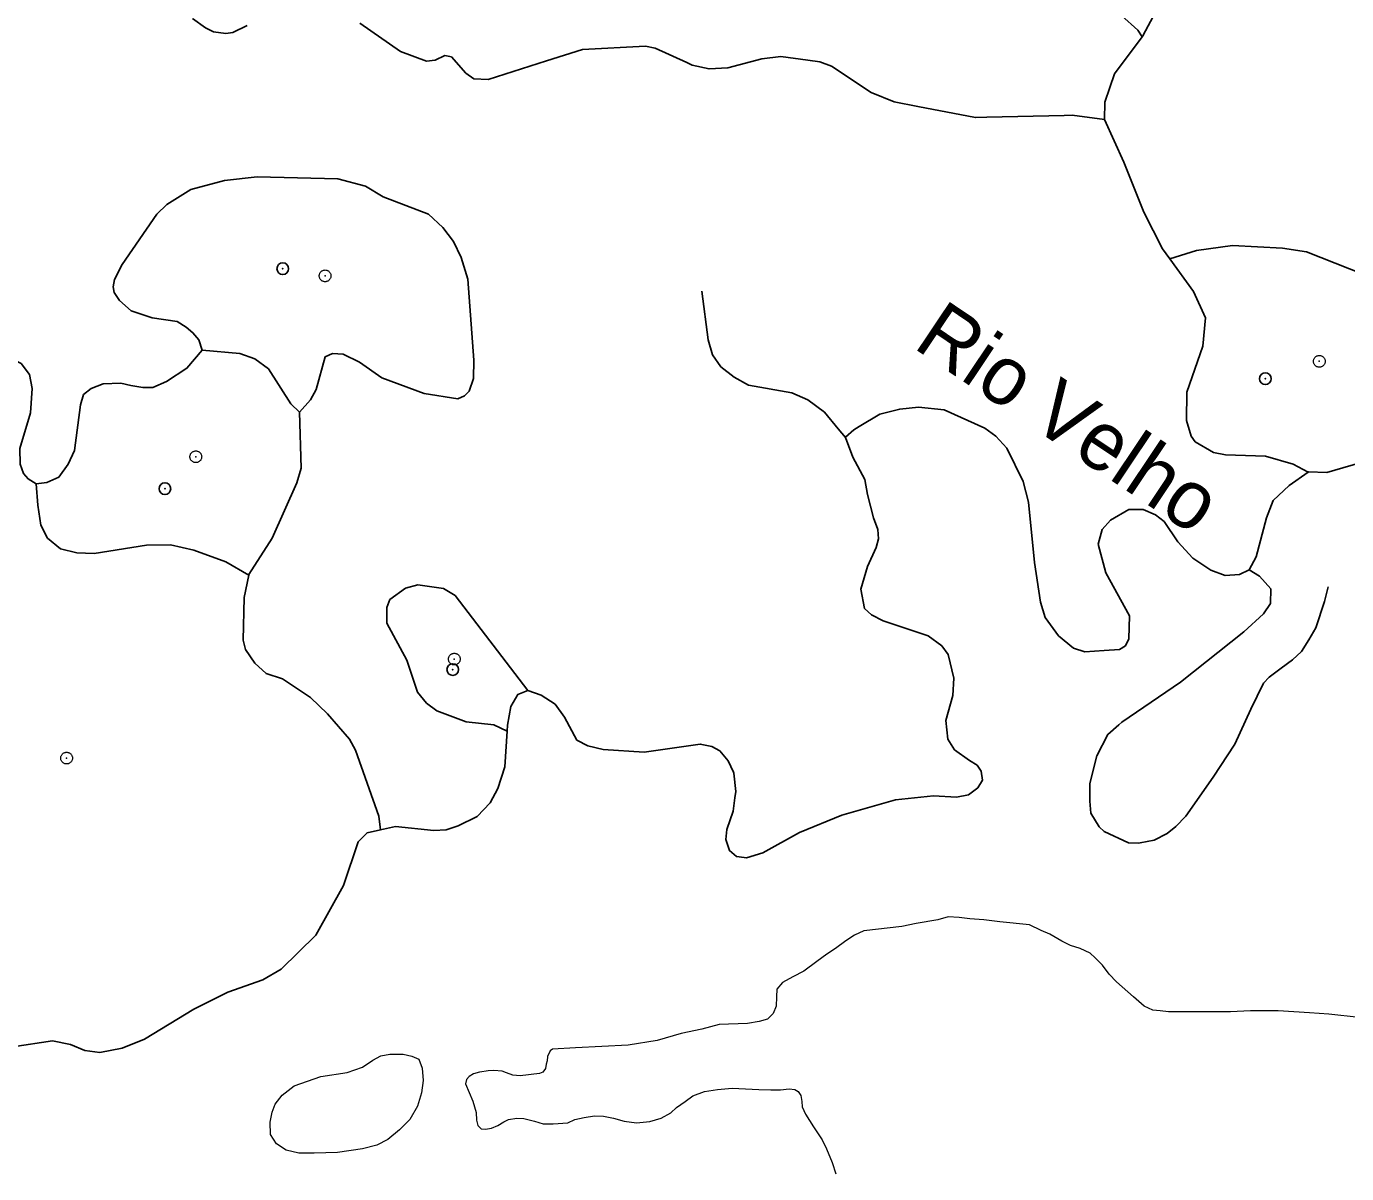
# Model space of a CAD drawing. Extents: x 267.7 to 296, y 7537.7 to 7565.8.
# Drawn here: x 272.267 to 274.519, y 7553.465 to 7555.422 of the extents above; entities that cross this region are included whole.
import ezdxf
from ezdxf.enums import TextEntityAlignment as Align

# ---------------------------------------------------------------- set-up
doc = ezdxf.new("R2010")
doc.units = 0
doc.header["$LTSCALE"] = 0.04
doc.header["$PDMODE"] = 32
doc.header["$PDSIZE"] = 0.02
doc.linetypes.add('SHORT_DASHED', pattern=[2.7, 1.5, -1.2])
doc.layers.add('21', color=7, linetype='SHORT_DASHED', lineweight=13)
doc.layers.add('7', color=7, linetype='Continuous', lineweight=25)
doc.layers.add('54', color=7, linetype='Continuous')
doc.layers.add('61', color=7, linetype='Continuous')

msp = doc.modelspace()

# ---------------------------------------------------------------- linework, layer by layer
at = {"layer": '21'}
for points in [[(274.5405, 7553.7312), (274.4887, 7553.7371), (274.4554, 7553.7394), (274.4022, 7553.7423), (274.3548, 7553.7423), (274.3208, 7553.7408), (274.2535, 7553.7408), (274.2306, 7553.7408), (274.2151, 7553.7408), (274.201, 7553.7423), (274.1884, 7553.7438), (274.1736, 7553.7504), (274.1552, 7553.7667), (274.1263, 7553.7919), (274.1137, 7553.8052), (274.1027, 7553.8207), (274.0901, 7553.8333), (274.0812, 7553.8407), (274.0642, 7553.8488), (274.0479, 7553.854), (274.0331, 7553.8614), (274.0124, 7553.8732), (273.9976, 7553.8799), (273.9777, 7553.8895), (273.9274, 7553.8947), (273.9, 7553.8976), (273.8764, 7553.8998), (273.8579, 7553.9021), (273.8394, 7553.9028), (273.8216, 7553.8976), (273.7847, 7553.8917), (273.7602, 7553.8865), (273.6952, 7553.8791), (273.6796, 7553.8717), (273.6648, 7553.8621), (273.6471, 7553.8488), (273.6323, 7553.8392), (273.6153, 7553.8266), (273.5931, 7553.8104)], [(273.5931, 7553.8104), (273.5746, 7553.8007), (273.5569, 7553.7911), (273.5473, 7553.7793), (273.5465, 7553.7667), (273.5458, 7553.7504)], [(273.5458, 7553.7504), (273.5406, 7553.7379), (273.531, 7553.7283), (273.5169, 7553.7246), (273.497, 7553.7209), (273.4489, 7553.7194), (273.4193, 7553.7113), (273.3838, 7553.7039), (273.3432, 7553.692), (273.2936, 7553.6839), (273.2034, 7553.6795), (273.1642, 7553.6772), (273.1605, 7553.6743), (273.156, 7553.6647), (273.1553, 7553.6573), (273.1538, 7553.6514), (273.1524, 7553.644), (273.1479, 7553.638), (273.142, 7553.6358), (273.1095, 7553.6314), (273.0969, 7553.6329), (273.0858, 7553.6366), (273.0784, 7553.6395), (273.0643, 7553.641), (273.0547, 7553.6403), (273.0407, 7553.638), (273.0399, 7553.638), (273.0296, 7553.6351), (273.0222, 7553.6306), (273.0178, 7553.6255), (273.0163, 7553.6181), (273.0222, 7553.6033), (273.0288, 7553.5885), (273.034, 7553.5693), (273.0348, 7553.556), (273.0372, 7553.5467), (273.0429, 7553.5412), (273.0503, 7553.5404), (273.0606, 7553.5426), (273.071, 7553.5471), (273.0814, 7553.553), (273.0895, 7553.5574), (273.1035, 7553.5596), (273.1154, 7553.5589), (273.1339, 7553.5545), (273.1487, 7553.55), (273.1657, 7553.55), (273.1908, 7553.5515), (273.2026, 7553.5574), (273.2182, 7553.5604), (273.2359, 7553.5633), (273.2514, 7553.5626), (273.2685, 7553.5596), (273.2869, 7553.5545), (273.3077, 7553.5515), (273.3306, 7553.5537), (273.3498, 7553.5596), (273.3661, 7553.5685), (273.3757, 7553.5774), (273.3905, 7553.5878), (273.4038, 7553.5974), (273.4238, 7553.6048), (273.4459, 7553.6085), (273.4711, 7553.6107), (273.5162, 7553.6085), (273.5369, 7553.6077), (273.5532, 7553.6077), (273.568, 7553.6092), (273.5776, 7553.6085), (273.5835, 7553.6048), (273.5879, 7553.5981), (273.5894, 7553.5878), (273.5902, 7553.5789), (273.5961, 7553.5663), (273.6094, 7553.5449), (273.6242, 7553.5227), (273.6316, 7553.5071), (273.6412, 7553.4835), (273.6478, 7553.4642)]]:
    msp.add_lwpolyline(points, dxfattribs=at)
msp.add_lwpolyline([(272.732, 7553.4997), (272.71, 7553.5048), (272.6938, 7553.5158), (272.6835, 7553.5313), (272.6827, 7553.5526), (272.6864, 7553.5695), (272.6916, 7553.5835), (272.7033, 7553.5989), (272.7239, 7553.6144), (272.7695, 7553.6306), (272.8144, 7553.6372), (272.8401, 7553.6467), (272.8578, 7553.6585), (272.8717, 7553.6659), (272.8872, 7553.6688), (272.91, 7553.6688), (272.9247, 7553.6651), (272.9364, 7553.66), (272.9423, 7553.6445), (272.9438, 7553.6239), (272.9408, 7553.6026), (272.9342, 7553.5798), (272.921, 7553.557), (272.9033, 7553.5394), (272.8835, 7553.5232), (272.8651, 7553.5136), (272.8401, 7553.507), (272.7975, 7553.5011), (272.7577, 7553.4997)], close=True, dxfattribs=at)
for p in [(272.7766, 7554.9968), (274.4722, 7554.851), (272.5561, 7554.6881), (272.997, 7554.3428), (272.3357, 7554.1738)]:
    msp.add_point(p, dxfattribs=at)
at = {"layer": '54'}
for p in [(272.7044, 7555.009), (274.3802, 7554.8213), (272.5033, 7554.6336), (272.9943, 7554.325)]:
    msp.add_point(p, dxfattribs=at)
at = {"layer": '7'}
for points in [[(274.1702, 7555.4048), (274.1713, 7555.4063), (274.1936, 7555.448), (274.1997, 7555.4594), (274.2058, 7555.4909), (274.2053, 7555.5587), (274.1908, 7555.6607), (274.1948, 7555.6876), (274.2191, 7555.7468), (274.2384, 7555.782)], [(273.9763, 7555.6484), (273.9954, 7555.6071), (274.0194, 7555.5646), (274.0368, 7555.5161), (274.0447, 7555.5036), (274.0653, 7555.4858), (274.0662, 7555.4849), (274.0939, 7555.4664), (274.1351, 7555.441), (274.163, 7555.4162), (274.1702, 7555.4048)], [(272.5502, 7555.4357), (272.5728, 7555.4203), (272.5861, 7555.4131), (272.6074, 7555.4103), (272.6195, 7555.4122), (272.6436, 7555.4239)], [(272.836, 7555.4282), (272.9053, 7555.3794), (272.9495, 7555.3633), (272.9642, 7555.365), (272.9809, 7555.3727), (272.9923, 7555.3705)], [(274.1058, 7555.2637), (274.1062, 7555.293), (274.1148, 7555.3182), (274.1227, 7555.3413), (274.1702, 7555.4048)], [(272.9923, 7555.3705), (273.0166, 7555.3427), (273.0301, 7555.3331), (273.0547, 7555.3319), (273.1543, 7555.3635), (273.2154, 7555.3828)], [(273.2154, 7555.3828), (273.323, 7555.3887), (273.3395, 7555.3854), (273.3934, 7555.3608), (273.4029, 7555.3565), (273.4315, 7555.3499), (273.4637, 7555.3517), (273.5217, 7555.3672), (273.5539, 7555.3713), (273.5997, 7555.365), (273.6205, 7555.3622), (273.6403, 7555.3546), (273.7079, 7555.3096), (273.7472, 7555.2937), (273.7878, 7555.2858), (273.8857, 7555.2669), (273.9054, 7555.2674), (274.0371, 7555.2706), (274.051, 7555.2709), (274.1058, 7555.2637)], [(274.2172, 7555.026), (274.2049, 7555.0429), (274.1729, 7555.1052), (274.1391, 7555.191), (274.1058, 7555.2637)], [(272.7329, 7554.7642), (272.7518, 7554.7855), (272.7615, 7554.803), (272.7767, 7554.8584), (272.7891, 7554.8645), (272.8074, 7554.8632), (272.8354, 7554.8493), (272.8736, 7554.8225), (272.9453, 7554.7962), (273.0031, 7554.7869), (273.0145, 7554.7921), (273.0225, 7554.8), (273.0298, 7554.8218), (273.0301, 7554.8527), (273.0203, 7554.991), (273.0088, 7555.0283), (272.9954, 7555.0555), (272.9775, 7555.0794), (272.9528, 7555.1019), (272.8758, 7555.1314), (272.8456, 7555.15), (272.7984, 7555.1626), (272.661, 7555.1656), (272.6051, 7555.1593), (272.5476, 7555.144), (272.5069, 7555.1185), (272.4895, 7555.102), (272.4304, 7555.0163), (272.4176, 7554.9906), (272.4151, 7554.9778), (272.417, 7554.9683), (272.4258, 7554.9549), (272.4456, 7554.937), (272.4817, 7554.925), (272.5244, 7554.9188), (272.5399, 7554.9091), (272.5511, 7554.8996), (272.5615, 7554.8875), (272.5667, 7554.8698)], [(274.6963, 7554.9579), (274.6766, 7554.9575), (274.6187, 7554.9714), (274.4505, 7555.0376), (274.4097, 7555.0441), (274.3243, 7555.0487), (274.2629, 7555.0399), (274.2172, 7555.026)], [(274.4531, 7554.6619), (274.4275, 7554.6755), (274.3805, 7554.6891), (274.3124, 7554.6912), (274.2916, 7554.6952), (274.2603, 7554.7137), (274.2535, 7554.7231), (274.246, 7554.7498), (274.2464, 7554.7985), (274.2738, 7554.8766), (274.2783, 7554.9253), (274.2579, 7554.9701), (274.2172, 7555.026)], [(273.419, 7554.9704), (273.4302, 7554.8875), (273.4375, 7554.8623), (273.4516, 7554.8417), (273.4742, 7554.8238), (273.4985, 7554.8101), (273.5724, 7554.7971), (273.5998, 7554.7855), (273.6281, 7554.7642), (273.6517, 7554.736), (273.6641, 7554.7211)], [(272.2003, 7554.8681), (272.2146, 7554.868), (272.2296, 7554.8621), (272.2581, 7554.8472), (272.2727, 7554.8282), (272.2772, 7554.8043), (272.2739, 7554.7629), (272.2557, 7554.7022), (272.2564, 7554.6755), (272.2621, 7554.6598), (272.27, 7554.6504), (272.284, 7554.6418)], [(272.284, 7554.6418), (272.3018, 7554.6443), (272.3223, 7554.6535), (272.3381, 7554.6755), (272.3494, 7554.6986), (272.3593, 7554.7767), (272.3644, 7554.7941), (272.3778, 7554.8044), (272.3983, 7554.8126), (272.4281, 7554.8136), (272.4455, 7554.8095), (272.466, 7554.8065), (272.4825, 7554.8065), (272.5061, 7554.8167), (272.5409, 7554.8391), (272.5667, 7554.8698)], [(272.5667, 7554.8698), (272.6313, 7554.8641), (272.6567, 7554.8553), (272.6802, 7554.8381), (272.7184, 7554.7784), (272.7329, 7554.7642)], [(272.7329, 7554.7642), (272.733, 7554.7641), (272.7356, 7554.6689), (272.7282, 7554.6434), (272.6863, 7554.5494), (272.6467, 7554.4874), (272.6465, 7554.4862)], [(273.6641, 7554.7211), (273.6639, 7554.7216), (273.6781, 7554.7343), (273.6877, 7554.74), (273.7227, 7554.7608), (273.7566, 7554.7695), (273.7885, 7554.7728), (273.8324, 7554.7679), (273.9017, 7554.7369), (273.9208, 7554.7233), (273.9391, 7554.7029), (273.9669, 7554.6459), (273.9761, 7554.6106), (273.9863, 7554.5076), (273.9969, 7554.4399), (274.0047, 7554.4136), (274.0276, 7554.3823), (274.0533, 7554.3615), (274.0721, 7554.3554), (274.1051, 7554.3576), (274.1314, 7554.3593), (274.1415, 7554.3655), (274.1476, 7554.3775), (274.1488, 7554.4169), (274.108, 7554.4902), (274.0951, 7554.5389), (274.1017, 7554.564), (274.1164, 7554.58), (274.1474, 7554.5979), (274.172, 7554.5979), (274.193, 7554.5892), (274.2074, 7554.5776), (274.2312, 7554.5428), (274.2568, 7554.5149), (274.2875, 7554.4947), (274.3117, 7554.4854), (274.3362, 7554.4872), (274.3526, 7554.495)], [(273.4619, 7554.0521), (273.4602, 7554.0352), (273.4665, 7554.016), (273.4781, 7554.0059), (273.4829, 7554.0053), (273.4955, 7554.0038), (273.5232, 7554.012), (273.5859, 7554.0471), (273.6577, 7554.0767), (273.7495, 7554.1026), (273.8145, 7554.1097), (273.8532, 7554.1071), (273.8738, 7554.1111), (273.8897, 7554.1229), (273.8979, 7554.1362), (273.8958, 7554.1516), (273.8886, 7554.1619), (273.8757, 7554.1695), (273.8501, 7554.1881), (273.8389, 7554.2063), (273.8353, 7554.2379), (273.8472, 7554.2804), (273.8492, 7554.31), (273.8393, 7554.3508), (273.8282, 7554.3653), (273.8049, 7554.3826), (273.7285, 7554.4082), (273.7085, 7554.4184), (273.6966, 7554.4292), (273.6904, 7554.4624), (273.7018, 7554.5006), (273.7162, 7554.5334), (273.7203, 7554.5478), (273.7193, 7554.5642), (273.7121, 7554.5837), (273.7018, 7554.6238), (273.697, 7554.6495), (273.6767, 7554.6876), (273.6641, 7554.7211)], [(274.4531, 7554.6619), (274.4538, 7554.6624), (274.4851, 7554.6613), (274.5574, 7554.6823), (274.6049, 7554.7002)], [(274.3526, 7554.495), (274.3648, 7554.5175), (274.3823, 7554.5841), (274.3937, 7554.6136), (274.4211, 7554.639), (274.4531, 7554.6619)], [(272.6465, 7554.4862), (272.6072, 7554.5086), (272.5526, 7554.5288), (272.5127, 7554.5377), (272.472, 7554.5372), (272.3827, 7554.5231), (272.353, 7554.5244), (272.3252, 7554.531), (272.3034, 7554.5492), (272.2916, 7554.5713), (272.2864, 7554.6053), (272.284, 7554.6418)], [(274.4874, 7554.4664), (274.4809, 7554.4411), (274.4665, 7554.3959), (274.4542, 7554.3754), (274.4419, 7554.3559), (274.4265, 7554.3415), (274.407, 7554.3271), (274.3865, 7554.3117), (274.3772, 7554.3015), (274.3557, 7554.2573), (274.3279, 7554.1978), (274.291, 7554.1413), (274.2444, 7554.0748), (274.2274, 7554.0572), (274.2126, 7554.0451), (274.1904, 7554.0336), (274.1668, 7554.0293), (274.1636, 7554.0287), (274.1467, 7554.029), (274.1055, 7554.0484), (274.0968, 7554.0567), (274.0826, 7554.0798), (274.0806, 7554.1003), (274.0809, 7554.1304), (274.0927, 7554.1778), (274.1113, 7554.2144), (274.1303, 7554.2307), (274.1357, 7554.2354), (274.2355, 7554.3036), (274.3436, 7554.3891), (274.3771, 7554.4202), (274.389, 7554.4376), (274.3893, 7554.4629), (274.3701, 7554.4841), (274.3526, 7554.495)], [(272.6465, 7554.4862), (272.6385, 7554.4477), (272.6371, 7554.3753), (272.6408, 7554.3592), (272.6565, 7554.3356), (272.676, 7554.3182), (272.7042, 7554.3094), (272.7518, 7554.277), (272.7804, 7554.2495), (272.8181, 7554.2063), (272.8284, 7554.1876), (272.8682, 7554.0747), (272.8712, 7554.0517)], [(273.1224, 7554.289), (272.9987, 7554.4513), (272.9788, 7554.4635), (272.935, 7554.4695), (272.9135, 7554.4638), (272.8868, 7554.4443), (272.8816, 7554.4309), (272.8821, 7554.4043), (272.9162, 7554.3408), (272.9339, 7554.2864), (272.9496, 7554.2677), (272.9673, 7554.2545), (273.0173, 7554.2355), (273.0641, 7554.2306), (273.0871, 7554.2201)], [(273.0871, 7554.2201), (273.0877, 7554.2301), (273.0931, 7554.2617), (273.1053, 7554.2825), (273.1224, 7554.289)], [(273.1224, 7554.289), (273.1451, 7554.281), (273.1689, 7554.266), (273.1848, 7554.2438), (273.2062, 7554.2047), (273.2245, 7554.195), (273.2506, 7554.1888), (273.3206, 7554.1841), (273.4164, 7554.1977), (273.4359, 7554.1937), (273.4498, 7554.186), (273.4641, 7554.1694), (273.4733, 7554.1498), (273.4739, 7554.1484), (273.4771, 7554.1169), (273.4756, 7554.1063), (273.4723, 7554.0833), (273.4619, 7554.0521)], [(272.8712, 7554.0517), (272.8967, 7554.0573), (272.9621, 7554.0503), (272.9828, 7554.0514), (273.0037, 7554.0581), (273.0358, 7554.0742), (273.0579, 7554.0977), (273.0713, 7554.122), (273.0833, 7554.1589), (273.0871, 7554.2201)], [(272.2442, 7553.6812), (272.3116, 7553.6913), (272.3421, 7553.6854), (272.3667, 7553.6747), (272.3922, 7553.6714), (272.4305, 7553.6788), (272.4688, 7553.6941), (272.5525, 7553.7457), (272.6109, 7553.7742), (272.6704, 7553.7954), (272.7019, 7553.8134), (272.761, 7553.8716), (272.808, 7553.9564), (272.8328, 7554.0311), (272.8481, 7554.0466), (272.8712, 7554.0517)]]:
    msp.add_lwpolyline(points, dxfattribs=at)

# ---------------------------------------------------------------- texts
at = {"layer": '61'}
msp.add_text('Rio Velho', height=0.1, rotation=326.192, dxfattribs=at).set_placement((274.0181, 7554.7139), align=Align.CENTER)

doc.saveas('drawing.dxf')
